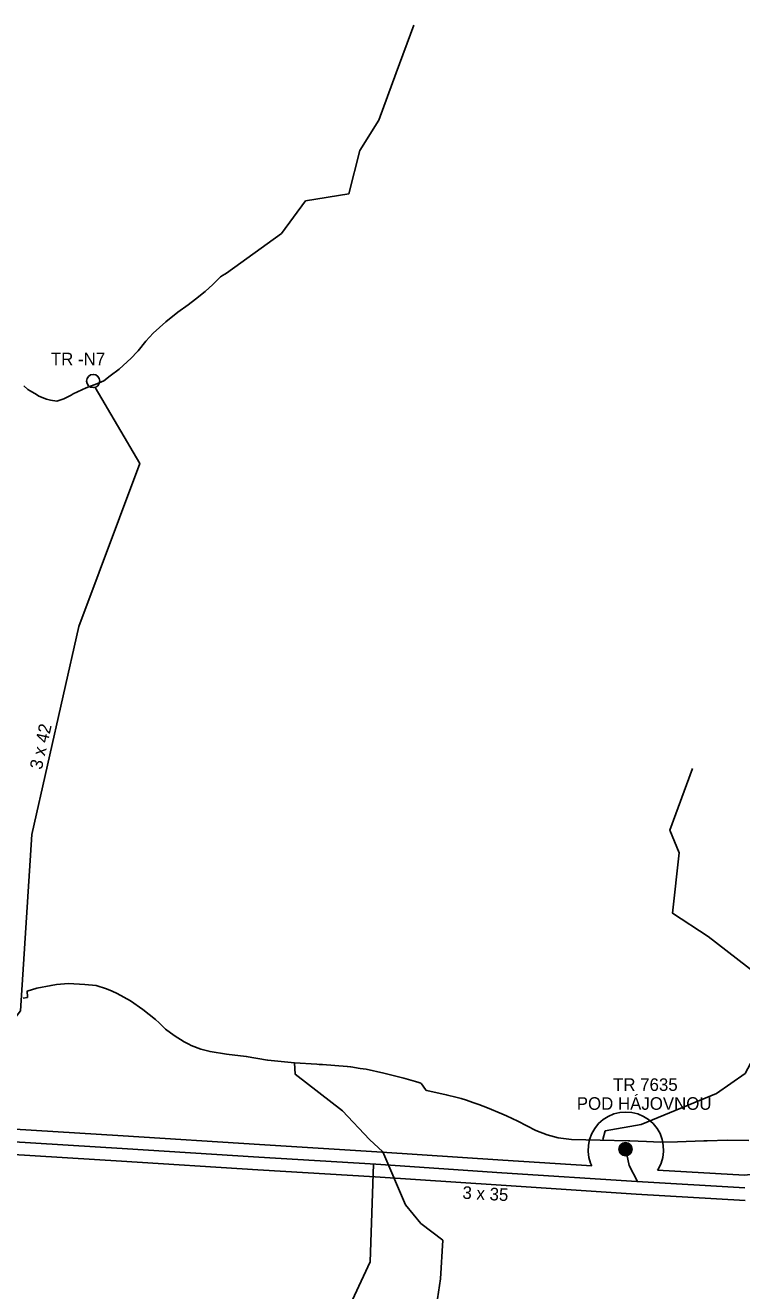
# Model space of a CAD drawing. Extents: x -439095 to -431527, y -1129525 to -1119219.
# Drawn here: x -437185 to -436616, y -1124404 to -1123399 of the extents above; entities that cross this region are included whole.
import ezdxf

# ---------------------------------------------------------------- set-up
doc = ezdxf.new("R2010")
doc.units = 0
for name, color, linetype in [('13861012_venkovní vedení elektrické sítě VN 1-35 kV_Stav', 7, 'Continuous'), ('14250012_plynovod STL_Stav', 7, 'Continuous'), ('14801013_OP vedení elektrické sítě_Stav', 7, 'Continuous'), ('Trafostanice', 7, 'Continuous'), ('Vrstva 13', 7, 'Continuous'), ('Vrstva 19', 7, 'Continuous'), ('Vrstva 21', 7, 'Continuous')]:
    doc.layers.add(name, color=color, linetype=linetype)

msp = doc.modelspace()

# ---------------------------------------------------------------- linework, layer by layer
at = {"layer": '13861012_venkovní vedení elektrické sítě VN 1-35 kV_Stav'}
for points in [[(-437129.4, -1123686.5), (-437093.8, -1123746.9), (-437142.4, -1123876.3), (-437179.6, -1124041.5), (-437188.5, -1124181.5), (-437266.5, -1124282.1)], [(-437197.9, -1124285.4), (-437107.9, -1124290.9), (-436999.5, -1124297.8), (-436906.4, -1124303.5), (-436806.3, -1124310.2), (-436699.2, -1124317.2), (-436613.5, -1124322.2)], [(-436698.7, -1124317.2), (-436705.4, -1124304.3), (-436707.9, -1124292)], [(-436908.2, -1124303.4), (-436911.1, -1124380.9), (-437003.6, -1124579.9)]]:
    msp.add_lwpolyline(points, dxfattribs=at)
at = {"layer": '14250012_plynovod STL_Stav'}
for points in [[(-437025.1, -1123595.7), (-436981.3, -1123564.2), (-436962.2, -1123538.4), (-436927.9, -1123532.7), (-436919.3, -1123498.3), (-436904, -1123474.4), (-436890.2, -1123436.7), (-436876.3, -1123399)], [(-437186, -1123685.4), (-437182.7, -1123688.1), (-437180.9, -1123689.3), (-437176, -1123692.2), (-437174, -1123693.4), (-437168, -1123695.9), (-437164.8, -1123696.8), (-437159.7, -1123697.4), (-437154.1, -1123695.7), (-437148.3, -1123692.6), (-437146.7, -1123691.7), (-437136.4, -1123687), (-437127.9, -1123683.6), (-437122.5, -1123681.2), (-437117.5, -1123677.4), (-437110.4, -1123672.1), (-437100.8, -1123663.3), (-437096, -1123658.3), (-437095.3, -1123657.6), (-437089.2, -1123649.7), (-437083.2, -1123643.4), (-437073.3, -1123634.6), (-437063.7, -1123626.8), (-437055.4, -1123621), (-437049.8, -1123616.5), (-437042, -1123610.5), (-437036, -1123604.9), (-437032.2, -1123601.1), (-437029.8, -1123598.7), (-437028.3, -1123597.8), (-437026.3, -1123596.5), (-437025.1, -1123595.7)], [(-436726.1, -1124283.9), (-436724.3, -1124276.9), (-436695.8, -1124271.9), (-436635.9, -1124247.3), (-436613.3, -1124231.5), (-436598.6, -1124204.1), (-436595.7, -1124158.9), (-436642.5, -1124122.7), (-436670.9, -1124104.1), (-436665.5, -1124056.1), (-436673.1, -1124038.1), (-436655, -1123989.1)], [(-437186.4, -1124171.5), (-437183.1, -1124170.9), (-437183, -1124170.6), (-437183.3, -1124166.1), (-437183.3, -1124165.9), (-437175.7, -1124163.6), (-437164.4, -1124161.4), (-437160, -1124160.6), (-437150.6, -1124159.9), (-437137.5, -1124160.8), (-437128.5, -1124161.6), (-437120.3, -1124164.1), (-437115.9, -1124166.1), (-437111.8, -1124167.9), (-437101.4, -1124173.7), (-437091.4, -1124180.6), (-437081.4, -1124188.4), (-437078.6, -1124191.2), (-437073.5, -1124196.2), (-437066.5, -1124201.3), (-437058.7, -1124206.2), (-437055, -1124208.2), (-437053.2, -1124209.2), (-437045.5, -1124212), (-437038.1, -1124214), (-437025.1, -1124215.9), (-437009.4, -1124217.8), (-436992.4, -1124220.7), (-436992.3, -1124220.8), (-436971.1, -1124222.8), (-436953.3, -1124224), (-436951.4, -1124224.1), (-436948.9, -1124224.3), (-436929.2, -1124225.7), (-436926.4, -1124226.2), (-436918.8, -1124227.3), (-436914.1, -1124228), (-436900.1, -1124231.2), (-436884.2, -1124235.1), (-436875, -1124237.8), (-436872.3, -1124238.6), (-436870.7, -1124239), (-436870.3, -1124239.5), (-436870.1, -1124239.6), (-436867, -1124244.2), (-436866.7, -1124244.5), (-436865.9, -1124244.9), (-436850.5, -1124248.2), (-436841.9, -1124250.3), (-436838.6, -1124251.1), (-436834.5, -1124252.5), (-436829.5, -1124254.3), (-436824.7, -1124256.1), (-436817.7, -1124258.6), (-436806.5, -1124263.4), (-436802.8, -1124265.1), (-436793.7, -1124269.2), (-436779.4, -1124276.7), (-436770.4, -1124280.2), (-436761.6, -1124282.5), (-436751.2, -1124283.8), (-436728.4, -1124284.3), (-436705.8, -1124284.8), (-436704.8, -1124284.8), (-436691.6, -1124285.5), (-436680.4, -1124285.9), (-436666.9, -1124285.6), (-436646, -1124284.9), (-436643.7, -1124284.8), (-436643.3, -1124284.8), (-436627.1, -1124284.4), (-436610.3, -1124284.5)], [(-436971.1, -1124222.8), (-436970.5, -1124232), (-436932.9, -1124261), (-436911.4, -1124283.8), (-436900.9, -1124293.7), (-436883, -1124335.6), (-436870.7, -1124350.4), (-436853.2, -1124363.8), (-436855.2, -1124394.3), (-436860.8, -1124431.4)]]:
    msp.add_lwpolyline(points, dxfattribs=at)
at = {"layer": '14801013_OP vedení elektrické sítě_Stav'}
for points in [[(-437793.3, -1124030.5), (-437769.7, -1124059.8), (-437717.4, -1124126.6), (-437648.4, -1124212.8), (-437589.1, -1124285.1), (-437554.1, -1124286.6), (-437507.9, -1124287.4), (-437408.6, -1124287.3), (-437307.5, -1124270.1), (-437197.4, -1124275.4), (-437107.2, -1124280.9), (-436998.9, -1124287.8), (-436905.8, -1124293.6), (-436805.6, -1124300.2), (-436735, -1124304.8)], [(-436682.7, -1124308.1), (-436613.8, -1124312.2), (-436538.1, -1124303.4), (-436456.4, -1124294.8), (-436388.8, -1124252.3), (-436310.5, -1124202.8), (-436202.1, -1124212.6), (-436123.9, -1124208.6), (-436042.2, -1124203.6), (-435968.1, -1124183.1), (-435885.5, -1124172.4), (-435784.3, -1124160.8), (-435726.6, -1124174.7), (-435726.6, -1124174.7), (-435716.7, -1124177.1)], [(-436735, -1124304.8), (-436736, -1124302.6), (-436737.3, -1124298), (-436737.9, -1124293.2), (-436737.7, -1124288.4), (-436736.7, -1124283.7), (-436735, -1124279.1), (-436732.6, -1124275), (-436729.6, -1124271.2), (-436726, -1124268), (-436721.9, -1124265.4), (-436717.4, -1124263.5), (-436712.7, -1124262.4), (-436707.9, -1124262), (-436703.1, -1124262.4), (-436698.4, -1124263.5), (-436694, -1124265.4), (-436689.9, -1124268), (-436686.3, -1124271.2), (-436683.2, -1124275), (-436680.8, -1124279.1), (-436679.1, -1124283.7), (-436678.2, -1124288.4), (-436678, -1124293.2), (-436678.5, -1124298), (-436679.9, -1124302.6), (-436682, -1124307), (-436682.7, -1124308.1)], [(-436613.2, -1124332.2), (-436699.8, -1124327.2), (-436807, -1124320.1), (-436907.1, -1124313.5), (-437000.2, -1124307.8), (-437108.5, -1124300.9), (-437198.4, -1124295.4), (-437306.3, -1124290.2), (-437406.9, -1124307.3), (-437508, -1124307.4), (-437554.5, -1124306.6), (-437554.6, -1124306.6), (-437580.4, -1124305.5)]]:
    msp.add_lwpolyline(points, dxfattribs=at)
at = {"layer": 'Trafostanice'}
for radius in [5.25, 4.55, 3.85, 3.15, 2.45, 1.75, 1.05, 0.35]:
    msp.add_circle((-436708.2, -1124291.5), radius, dxfattribs=at)
at = {"layer": 'Vrstva 19'}
msp.add_circle((-437130.9, -1123681.5), 5.25, dxfattribs=at)

# ---------------------------------------------------------------- texts
at = {"layer": 'Vrstva 13'}
for s, rotation, p in [('3 x 42', 77.4278, (-437171.7, -1123990.5)), ('3 x 35', 356.971, (-436837.9, -1124330.8))]:
    msp.add_text(s, height=10, rotation=rotation, dxfattribs=at).set_placement(p)
for s, p in [('TR 7635', (-436718.1, -1124245.2)), ('POD HÁJOVNOU', (-436746.9, -1124260.2))]:
    msp.add_text(s, height=10, dxfattribs=at).set_placement(p)
at = {"layer": 'Vrstva 21'}
msp.add_text('TR -N7', height=10, dxfattribs=at).set_placement((-437164.5, -1123669))

doc.saveas('drawing.dxf')
